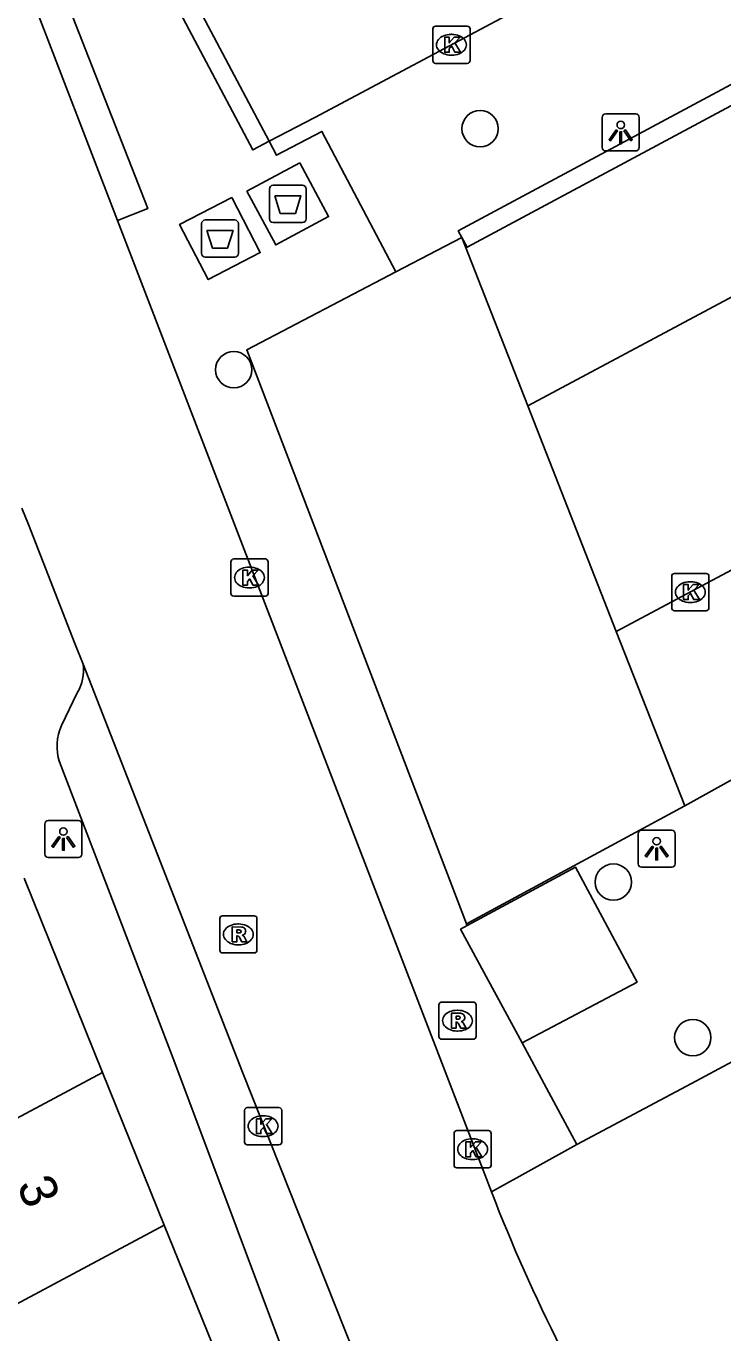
# Model space of a CAD drawing. Extents: x 160304 to 160954, y 383686 to 384161.
# Drawn here: x 160780.26 to 160799.01, y 383904.41 to 383939.55 of the extents above; entities that cross this region are included whole.
import ezdxf

# ---------------------------------------------------------------- set-up
doc = ezdxf.new("R2010")
doc.units = 0
for name, color, linetype in [('IMGEO_Afval_apart_plaats', 7, 'Continuous'), ('IMGEO_Boom', 7, 'Continuous'), ('IMGEO_Kolk', 7, 'Continuous'), ('IMGEO_Lichtpunt', 7, 'Continuous'), ('IMGEO_Pand', 7, 'Continuous'), ('IMGEO_Pand_nummerreeks', 7, 'Continuous'), ('IMGEO_Parkeervlak_open', 7, 'Continuous'), ('IMGEO_Rijbaan_lokaal_open', 7, 'Continuous'), ('IMGEO_Rioolput', 7, 'Continuous'), ('IMGEO_Voetpad_gesloten', 7, 'Continuous'), ('IMGEO_Voetpad_open', 7, 'Continuous')]:
    doc.layers.add(name, color=color, linetype=linetype)

msp = doc.modelspace()

# ---------------------------------------------------------------- linework, layer by layer
at = {"layer": 'IMGEO_Afval_apart_plaats'}
for p, q in [((160786.808, 383934.373), (160786.808, 383935.173)), ((160786.808, 383935.173), (160786.808, 383934.373)), ((160786.908, 383935.273), (160787.698, 383935.273)), ((160787.698, 383935.273), (160786.908, 383935.273)), ((160787.798, 383935.173), (160787.798, 383934.373)), ((160787.798, 383934.373), (160787.798, 383935.173)), ((160784.984, 383933.442), (160784.984, 383934.242)), ((160784.984, 383934.242), (160784.984, 383933.442)), ((160785.084, 383934.342), (160785.874, 383934.342)), ((160785.874, 383934.342), (160785.084, 383934.342)), ((160785.974, 383934.242), (160785.974, 383933.442)), ((160785.974, 383933.442), (160785.974, 383934.242)), ((160787.698, 383934.273), (160786.908, 383934.273)), ((160786.908, 383934.273), (160787.698, 383934.273)), ((160785.874, 383933.342), (160785.084, 383933.342)), ((160785.084, 383933.342), (160785.874, 383933.342))]:
    msp.add_line(p, q, dxfattribs=at)
for points in [[(160786.951, 383934.987), (160787.655, 383934.987), (160787.506, 383934.517), (160787.1, 383934.517), (160786.951, 383934.987)], [(160785.127, 383934.056), (160785.831, 383934.056), (160785.682, 383933.586), (160785.276, 383933.586), (160785.127, 383934.056)]]:
    msp.add_lwpolyline(points, dxfattribs=at)
for centre, start, end in [((160786.908, 383935.173), 90, 180), ((160786.908, 383935.173), 90, 180), ((160787.698, 383935.173), 0, 90), ((160787.698, 383935.173), 360, 90), ((160785.084, 383934.242), 90, 180), ((160785.084, 383934.242), 90, 180), ((160785.874, 383934.242), 0, 90), ((160785.874, 383934.242), 360, 90), ((160786.908, 383934.373), 180, 270), ((160786.908, 383934.373), 180, 270), ((160787.698, 383934.373), 270, 0), ((160787.698, 383934.373), 270, 0), ((160785.084, 383933.442), 180, 270), ((160785.084, 383933.442), 180, 270), ((160785.874, 383933.442), 270, 0), ((160785.874, 383933.442), 270, 0)]:
    msp.add_arc(centre, 0.1, start, end, dxfattribs=at)
at = {"layer": 'IMGEO_Boom'}
for centre in [(160792.476, 383936.796), (160785.849, 383930.313), (160796.061, 383916.532), (160798.197, 383912.35)]:
    msp.add_circle(centre, 0.489, dxfattribs=at)
at = {"layer": 'IMGEO_Kolk'}
for p, q in [((160791.204, 383938.628), (160791.204, 383939.48)), ((160791.279, 383939.554), (160792.131, 383939.554)), ((160791.692, 383939.334), (160791.717, 383939.334)), ((160792.205, 383939.48), (160792.205, 383938.628)), ((160791.715, 383938.774), (160791.69, 383938.774)), ((160792.131, 383938.554), (160791.279, 383938.554)), ((160785.772, 383924.297), (160785.772, 383925.149)), ((160785.847, 383925.223), (160786.699, 383925.223)), ((160786.26, 383925.003), (160786.285, 383925.003)), ((160786.773, 383925.149), (160786.773, 383924.297)), ((160797.63, 383923.907), (160797.63, 383924.759)), ((160797.705, 383924.833), (160798.557, 383924.833)), ((160798.118, 383924.613), (160798.143, 383924.613)), ((160798.631, 383924.759), (160798.631, 383923.907)), ((160786.699, 383924.223), (160785.847, 383924.223)), ((160786.283, 383924.443), (160786.258, 383924.443)), ((160798.141, 383924.053), (160798.116, 383924.053)), ((160798.557, 383923.833), (160797.705, 383923.833)), ((160786.138, 383909.541), (160786.138, 383910.393)), ((160786.213, 383910.467), (160787.065, 383910.467)), ((160786.626, 383910.247), (160786.651, 383910.247)), ((160787.139, 383910.393), (160787.139, 383909.541)), ((160791.849, 383909.848), (160792.701, 383909.848)), ((160787.065, 383909.467), (160786.213, 383909.467)), ((160786.649, 383909.687), (160786.624, 383909.687)), ((160791.774, 383908.922), (160791.774, 383909.774)), ((160792.262, 383909.628), (160792.287, 383909.628)), ((160792.775, 383909.774), (160792.775, 383908.922)), ((160792.701, 383908.848), (160791.849, 383908.848)), ((160792.285, 383909.068), (160792.26, 383909.068))]:
    msp.add_line(p, q, dxfattribs=at)
for points in [[(160791.204, 383938.628), (160791.204, 383939.48)], [(160791.279, 383939.554), (160792.131, 383939.554)], [(160792.205, 383939.48), (160792.205, 383938.628)], [(160791.525, 383939.254), (160791.648, 383939.254), (160791.648, 383939.103), (160791.778, 383939.254), (160791.942, 383939.254), (160791.796, 383939.103), (160791.949, 383938.854), (160791.797, 383938.854), (160791.712, 383939.018), (160791.648, 383938.951), (160791.648, 383938.854), (160791.525, 383938.854), (160791.525, 383939.254)], [(160792.131, 383938.554), (160791.279, 383938.554)], [(160785.772, 383924.297), (160785.772, 383925.149)], [(160785.847, 383925.223), (160786.699, 383925.223)], [(160786.093, 383924.923), (160786.216, 383924.923), (160786.216, 383924.772), (160786.346, 383924.923), (160786.51, 383924.923), (160786.364, 383924.772), (160786.517, 383924.523), (160786.365, 383924.523), (160786.28, 383924.687), (160786.216, 383924.62), (160786.216, 383924.523), (160786.093, 383924.523), (160786.093, 383924.923)], [(160786.773, 383925.149), (160786.773, 383924.297)], [(160797.63, 383923.907), (160797.63, 383924.759)], [(160797.705, 383924.833), (160798.557, 383924.833)], [(160798.631, 383924.759), (160798.631, 383923.907)], [(160786.699, 383924.223), (160785.847, 383924.223)], [(160797.951, 383924.533), (160798.074, 383924.533), (160798.074, 383924.382), (160798.204, 383924.533), (160798.368, 383924.533), (160798.222, 383924.382), (160798.375, 383924.133), (160798.223, 383924.133), (160798.138, 383924.297), (160798.074, 383924.23), (160798.074, 383924.133), (160797.951, 383924.133), (160797.951, 383924.533)], [(160798.557, 383923.833), (160797.705, 383923.833)], [(160786.138, 383909.541), (160786.138, 383910.393)], [(160786.213, 383910.467), (160787.065, 383910.467)], [(160786.459, 383910.167), (160786.582, 383910.167), (160786.582, 383910.016), (160786.712, 383910.167), (160786.876, 383910.167), (160786.73, 383910.016), (160786.883, 383909.767), (160786.731, 383909.767), (160786.646, 383909.931), (160786.582, 383909.864), (160786.582, 383909.767), (160786.459, 383909.767), (160786.459, 383910.167)], [(160787.139, 383910.393), (160787.139, 383909.541)], [(160791.849, 383909.848), (160792.701, 383909.848)], [(160787.065, 383909.467), (160786.213, 383909.467)], [(160791.774, 383908.922), (160791.774, 383909.774)], [(160792.095, 383909.548), (160792.218, 383909.548), (160792.218, 383909.397), (160792.348, 383909.548), (160792.512, 383909.548), (160792.366, 383909.397), (160792.519, 383909.148), (160792.367, 383909.148), (160792.282, 383909.312), (160792.218, 383909.245), (160792.218, 383909.148), (160792.095, 383909.148), (160792.095, 383909.548)], [(160792.775, 383909.774), (160792.775, 383908.922)], [(160792.701, 383908.848), (160791.849, 383908.848)]]:
    msp.add_lwpolyline(points, dxfattribs=at)
for centre, start, end in [((160791.281, 383939.478), 91.552, 178.448), ((160791.281, 383939.478), 91.552, 178.448), ((160792.129, 383939.478), 1.552, 88.448), ((160792.129, 383939.478), 1.552, 88.448), ((160791.281, 383938.63), 181.552, 268.448), ((160791.281, 383938.63), 181.552, 268.448), ((160792.129, 383938.63), 271.552, 358.448), ((160792.129, 383938.63), 271.552, 358.448), ((160785.849, 383925.147), 91.552, 178.448), ((160785.849, 383925.147), 91.552, 178.448), ((160786.697, 383925.147), 1.552, 88.448), ((160786.697, 383925.147), 1.552, 88.448), ((160797.707, 383924.757), 91.552, 178.448), ((160797.707, 383924.757), 91.552, 178.448), ((160798.555, 383924.757), 1.552, 88.448), ((160798.555, 383924.757), 1.552, 88.448), ((160785.849, 383924.299), 181.552, 268.448), ((160785.849, 383924.299), 181.552, 268.448), ((160786.697, 383924.299), 271.552, 358.448), ((160786.697, 383924.299), 271.552, 358.448), ((160797.707, 383923.909), 181.552, 268.448), ((160797.707, 383923.909), 181.552, 268.448), ((160798.555, 383923.909), 271.552, 358.448), ((160798.555, 383923.909), 271.552, 358.448), ((160786.215, 383910.391), 91.552, 178.448), ((160786.215, 383910.391), 91.552, 178.448), ((160787.063, 383910.391), 1.552, 88.448), ((160787.063, 383910.391), 1.552, 88.448), ((160791.851, 383909.772), 91.552, 178.448), ((160791.851, 383909.772), 91.552, 178.448), ((160792.699, 383909.772), 1.552, 88.448), ((160792.699, 383909.772), 1.552, 88.448), ((160786.215, 383909.543), 181.552, 268.448), ((160786.215, 383909.543), 181.552, 268.448), ((160787.063, 383909.543), 271.552, 358.448), ((160787.063, 383909.543), 271.552, 358.448), ((160791.851, 383908.924), 181.552, 268.448), ((160791.851, 383908.924), 181.552, 268.448), ((160792.699, 383908.924), 271.552, 358.448), ((160792.699, 383908.924), 271.552, 358.448)]:
    msp.add_arc(centre, 0.0765, start, end, dxfattribs=at)
for centre, major_axis, ratio, start_param, end_param in [((160791.691, 383939.054), (-0.387, 0.002), 0.722429, 4.712389, 7.853982), ((160791.716, 383939.054), (-0.39, 0.002), 0.717154, 1.570796, 4.712389), ((160786.259, 383924.723), (-0.387, 0.002), 0.722429, 4.712389, 7.853982), ((160786.284, 383924.723), (-0.39, 0.002), 0.717154, 1.570796, 4.712389), ((160798.117, 383924.333), (-0.387, 0.002), 0.722429, 4.712389, 7.853982), ((160798.142, 383924.333), (-0.39, 0.002), 0.717154, 1.570796, 4.712389), ((160786.625, 383909.967), (-0.387, 0.002), 0.722429, 4.712389, 7.853982), ((160786.65, 383909.967), (-0.39, 0.002), 0.717154, 1.570796, 4.712389), ((160792.261, 383909.348), (-0.387, 0.002), 0.722429, 4.712389, 7.853982), ((160792.286, 383909.348), (-0.39, 0.002), 0.717154, 1.570796, 4.712389)]:
    msp.add_ellipse(centre, major_axis=major_axis, ratio=ratio, start_param=start_param, end_param=end_param, dxfattribs=at)
at = {"layer": 'IMGEO_Lichtpunt'}
for p, q in [((160795.76, 383937.099), (160795.76, 383936.292)), ((160795.76, 383937.099), (160795.76, 383936.292)), ((160796.662, 383937.194), (160795.854, 383937.194)), ((160796.662, 383937.194), (160795.854, 383937.194)), ((160796.756, 383936.292), (160796.756, 383937.099)), ((160796.756, 383936.292), (160796.756, 383937.099)), ((160795.854, 383936.198), (160796.662, 383936.198)), ((160795.854, 383936.198), (160796.662, 383936.198)), ((160780.767, 383918.094), (160780.767, 383917.287)), ((160780.767, 383918.094), (160780.767, 383917.287)), ((160781.669, 383918.189), (160780.861, 383918.189)), ((160781.669, 383918.189), (160780.861, 383918.189)), ((160781.763, 383917.287), (160781.763, 383918.094)), ((160781.763, 383917.287), (160781.763, 383918.094)), ((160797.629, 383917.929), (160796.821, 383917.929)), ((160797.629, 383917.929), (160796.821, 383917.929)), ((160796.727, 383917.834), (160796.727, 383917.027)), ((160796.727, 383917.834), (160796.727, 383917.027)), ((160797.723, 383917.027), (160797.723, 383917.834)), ((160797.723, 383917.027), (160797.723, 383917.834)), ((160780.861, 383917.193), (160781.669, 383917.193)), ((160780.861, 383917.193), (160781.669, 383917.193)), ((160796.821, 383916.933), (160797.629, 383916.933)), ((160796.821, 383916.933), (160797.629, 383916.933))]:
    msp.add_line(p, q, dxfattribs=at)
for points in [[(160796.134, 383936.763), (160796.173, 383936.735), (160795.985, 383936.473), (160795.947, 383936.5), (160796.134, 383936.763)], [(160796.236, 383936.715), (160796.283, 383936.715), (160796.283, 383936.393), (160796.236, 383936.393), (160796.236, 383936.715)], [(160796.346, 383936.735), (160796.384, 383936.762), (160796.571, 383936.5), (160796.532, 383936.472), (160796.346, 383936.735)], [(160781.141, 383917.758), (160781.18, 383917.73), (160780.992, 383917.468), (160780.954, 383917.495), (160781.141, 383917.758)], [(160781.243, 383917.71), (160781.29, 383917.71), (160781.29, 383917.388), (160781.243, 383917.388), (160781.243, 383917.71)], [(160781.353, 383917.73), (160781.391, 383917.757), (160781.578, 383917.495), (160781.539, 383917.467), (160781.353, 383917.73)], [(160797.101, 383917.498), (160797.14, 383917.47), (160796.952, 383917.208), (160796.914, 383917.235), (160797.101, 383917.498)], [(160797.203, 383917.45), (160797.25, 383917.45), (160797.25, 383917.128), (160797.203, 383917.128), (160797.203, 383917.45)], [(160797.313, 383917.47), (160797.351, 383917.497), (160797.538, 383917.235), (160797.499, 383917.207), (160797.313, 383917.47)]]:
    msp.add_lwpolyline(points, dxfattribs=at)
for centre in [(160796.259, 383936.897), (160781.266, 383917.892), (160797.226, 383917.632)]:
    msp.add_circle(centre, 0.0994, dxfattribs=at)
for centre, start, end in [((160795.854, 383937.099), 90, 180), ((160795.854, 383937.099), 90, 180), ((160796.662, 383937.099), 0, 90), ((160796.662, 383937.099), 0, 90), ((160795.854, 383936.292), 180, 270), ((160795.854, 383936.292), 180, 270), ((160796.662, 383936.292), 270, 0), ((160796.662, 383936.292), 270, 360), ((160780.861, 383918.094), 90, 180), ((160780.861, 383918.094), 90, 180), ((160781.669, 383918.094), 0, 90), ((160781.669, 383918.094), 0, 90), ((160796.821, 383917.834), 90, 180), ((160796.821, 383917.834), 90, 180), ((160797.629, 383917.834), 0, 90), ((160797.629, 383917.834), 0, 90), ((160780.861, 383917.287), 180, 270), ((160780.861, 383917.287), 180, 270), ((160781.669, 383917.287), 270, 0), ((160781.669, 383917.287), 270, 360), ((160796.821, 383917.027), 180, 270), ((160796.821, 383917.027), 180, 270), ((160797.629, 383917.027), 270, 0), ((160797.629, 383917.027), 270, 360)]:
    msp.add_arc(centre, 0.0946, start, end, dxfattribs=at)
at = {"layer": 'IMGEO_Pand'}
for points in [[(160790.207, 383932.944), (160791.984, 383933.871)], [(160791.984, 383933.871), (160793.759, 383929.343)], [(160792.114, 383915.415), (160786.198, 383930.852), (160790.207, 383932.944)], [(160793.759, 383929.343), (160796.14, 383923.272)], [(160796.14, 383923.272), (160797.98, 383918.581)], [(160792.114, 383915.415), (160797.98, 383918.581)], [(160793.605, 383912.207), (160796.7, 383913.845), (160795.901, 383915.334), (160795.04, 383916.939), (160792.132, 383915.366)], [(160780.213, 383916.636), (160782.322, 383911.415)], [(160793.605, 383912.207), (160791.95, 383915.267), (160792.132, 383915.366)], [(160782.322, 383911.415), (160772.771, 383906.312)], [(160782.322, 383911.415), (160783.981, 383907.309)], [(160774.429, 383902.206), (160783.981, 383907.309)], [(160783.981, 383907.309), (160785.767, 383902.886), (160785.538, 383902.764)]]:
    msp.add_lwpolyline(points, dxfattribs=at)
at = {"layer": 'IMGEO_Parkeervlak_open'}
for points in [[(160811.073, 383944.262), (160811.041, 383944.322), (160791.889, 383934.047), (160791.984, 383933.871)], [(160791.984, 383933.871), (160792.126, 383933.607), (160811.278, 383943.881), (160811.073, 383944.262)], [(160797.98, 383918.581), (160800, 383919.705), (160803.043, 383921.331)]]:
    msp.add_lwpolyline(points, dxfattribs=at)
at = {"layer": 'IMGEO_Rijbaan_lokaal_open'}
for points in [[(160810.678, 383946.827), (160809.733, 383948.656), (160788.027, 383937.097), (160786.802, 383936.458)], [(160783.989, 383941.774), (160786.802, 383936.458)], [(160793.759, 383929.343), (160814.156, 383940.234), (160813.481, 383941.466)], [(160782.721, 383934.328), (160780.378, 383940.412)], [(160796.14, 383923.272), (160817.571, 383934.699)], [(160792.783, 383908.2), (160782.721, 383934.328)], [(160780.153, 383926.593), (160780.327, 383926.147), (160781.576, 383922.953), (160781.796, 383922.391)], [(160781.796, 383922.391), (160786.081, 383911.423), (160789.845, 383901.965)]]:
    msp.add_lwpolyline(points, dxfattribs=at)
msp.add_arc((160837.374, 383925.492), 47.827, 201.1959, 206.6782, dxfattribs=at)
at = {"layer": 'IMGEO_Rioolput'}
for p, q in [((160785.473, 383914.701), (160785.473, 383915.553)), ((160785.548, 383915.627), (160786.4, 383915.627)), ((160786.474, 383915.553), (160786.474, 383914.701)), ((160785.961, 383915.407), (160785.986, 383915.407)), ((160785.984, 383914.847), (160785.959, 383914.847)), ((160786.4, 383914.627), (160785.548, 383914.627)), ((160791.367, 383912.38), (160791.367, 383913.232)), ((160791.442, 383913.306), (160792.294, 383913.306)), ((160791.855, 383913.086), (160791.88, 383913.086)), ((160792.368, 383913.232), (160792.368, 383912.38)), ((160792.294, 383912.306), (160791.442, 383912.306)), ((160791.878, 383912.526), (160791.853, 383912.526))]:
    msp.add_line(p, q, dxfattribs=at)
for points in [[(160785.473, 383914.701), (160785.473, 383915.553)], [(160785.548, 383915.627), (160786.4, 383915.627)], [(160786.474, 383915.553), (160786.474, 383914.701)], [(160786.062, 383915.325), (160785.81, 383915.327), (160785.81, 383914.927)], [(160785.81, 383914.927), (160785.934, 383914.927), (160785.934, 383915.089), (160785.945, 383915.089)], [(160785.988, 383915.246), (160785.934, 383915.246), (160785.934, 383915.165)], [(160785.934, 383915.165), (160785.986, 383915.165)], [(160785.992, 383915.06), (160786.063, 383914.927), (160786.203, 383914.927), (160786.138, 383915.053)], [(160786.4, 383914.627), (160785.548, 383914.627)], [(160791.367, 383912.38), (160791.367, 383913.232)], [(160791.442, 383913.306), (160792.294, 383913.306)], [(160791.956, 383913.004), (160791.704, 383913.006), (160791.704, 383912.606)], [(160792.368, 383913.232), (160792.368, 383912.38)], [(160791.704, 383912.606), (160791.828, 383912.606), (160791.828, 383912.768), (160791.839, 383912.768)], [(160791.882, 383912.925), (160791.828, 383912.925), (160791.828, 383912.844)], [(160791.828, 383912.844), (160791.88, 383912.844)], [(160791.886, 383912.739), (160791.957, 383912.606), (160792.097, 383912.606), (160792.032, 383912.732)], [(160792.294, 383912.306), (160791.442, 383912.306)]]:
    msp.add_lwpolyline(points, dxfattribs=at)
for centre, radius, start, end in [((160785.55, 383915.551), 0.0765, 91.552, 178.448), ((160785.55, 383915.551), 0.0765, 91.552, 178.448), ((160786.398, 383915.551), 0.0765, 1.552, 88.448), ((160786.398, 383915.551), 0.0765, 1.552, 88.448), ((160785.944, 383915.036), 0.0533, 26.0293, 88.6989), ((160785.97, 383915.354), 0.19, 274.7715, 282.9687), ((160785.994, 383915.15), 0.0964, 77.0061, 93.1865), ((160786.008, 383915.207), 0.0378, 276.6634, 79.6772), ((160786.061, 383915.215), 0.109, 350.3612, 89.416), ((160786.059, 383915.215), 0.112, 277.5842, 350.9817), ((160786.043, 383915), 0.108, 29.5134, 73.7905), ((160785.55, 383914.703), 0.0765, 181.552, 268.448), ((160785.55, 383914.703), 0.0765, 181.552, 268.448), ((160786.398, 383914.703), 0.0765, 271.552, 358.448), ((160786.398, 383914.703), 0.0765, 271.552, 358.448), ((160791.444, 383913.23), 0.0765, 91.552, 178.448), ((160791.444, 383913.23), 0.0765, 91.552, 178.448), ((160791.955, 383912.894), 0.109, 350.3612, 89.416), ((160792.292, 383913.23), 0.0765, 1.552, 88.448), ((160792.292, 383913.23), 0.0765, 1.552, 88.448), ((160791.838, 383912.715), 0.0533, 26.0293, 88.6989), ((160791.864, 383913.033), 0.19, 274.7715, 282.9687), ((160791.888, 383912.829), 0.0964, 77.0061, 93.1865), ((160791.902, 383912.886), 0.0378, 276.6634, 79.6772), ((160791.953, 383912.894), 0.112, 277.5842, 350.9817), ((160791.937, 383912.679), 0.108, 29.5134, 73.7905), ((160791.444, 383912.382), 0.0765, 181.552, 268.448), ((160791.444, 383912.382), 0.0765, 181.552, 268.448), ((160792.292, 383912.382), 0.0765, 271.552, 358.448), ((160792.292, 383912.382), 0.0765, 271.552, 358.448)]:
    msp.add_arc(centre, radius, start, end, dxfattribs=at)
for centre, major_axis, ratio, start_param, end_param in [((160785.96, 383915.127), (-0.387, 0.002), 0.722429, 4.712389, 7.853982), ((160785.985, 383915.127), (-0.39, 0.002), 0.717154, 1.570796, 4.712389), ((160791.854, 383912.806), (-0.387, 0.002), 0.722429, 4.712389, 7.853982), ((160791.879, 383912.806), (-0.39, 0.002), 0.717154, 1.570796, 4.712389)]:
    msp.add_ellipse(centre, major_axis=major_axis, ratio=ratio, start_param=start_param, end_param=end_param, dxfattribs=at)
at = {"layer": 'IMGEO_Voetpad_gesloten'}
for points in [[(160787.63, 383935.875), (160788.402, 383934.434), (160786.977, 383933.671), (160786.205, 383935.112), (160787.63, 383935.875)], [(160785.794, 383934.948), (160786.564, 383933.462), (160785.164, 383932.737), (160784.394, 383934.223), (160785.794, 383934.948)]]:
    msp.add_lwpolyline(points, dxfattribs=at)
at = {"layer": 'IMGEO_Voetpad_open'}
for points in [[(160786.802, 383936.458), (160786.361, 383936.224), (160783.548, 383941.54), (160783.989, 383941.774)], [(160780.378, 383940.412), (160781.166, 383940.72), (160783.537, 383934.647), (160782.721, 383934.328)], [(160786.802, 383936.458), (160787.001, 383936.082), (160788.223, 383936.724), (160790.207, 383932.944)], [(160781.214, 383920.746), (160781.64, 383921.624)], [(160789.823, 383897.696), (160787.618, 383902.725), (160784.265, 383911.672), (160781.163, 383919.764)], [(160792.132, 383915.366), (160792.114, 383915.415)], [(160805.18, 383905.196), (160804.784, 383904.985), (160800.773, 383912.513), (160799.631, 383911.906), (160798.165, 383911.113), (160795.078, 383909.479)], [(160795.078, 383909.479), (160794.261, 383910.993), (160793.605, 383912.207)], [(160795.078, 383909.479), (160792.783, 383908.2)]]:
    msp.add_lwpolyline(points, dxfattribs=at)
for centre, radius, start, end in [((160780.626, 383922.23), 1.181, 329.1598, 7.8471), ((160782.442, 383920.19), 1.348, 155.637, 198.4171)]:
    msp.add_arc(centre, radius, start, end, dxfattribs=at)

# ---------------------------------------------------------------- texts
at = {"layer": 'IMGEO_Pand_nummerreeks'}
msp.add_text('3', height=1, rotation=291.9888, dxfattribs=at).set_placement((160780.005, 383908.388))

doc.saveas('drawing.dxf')
